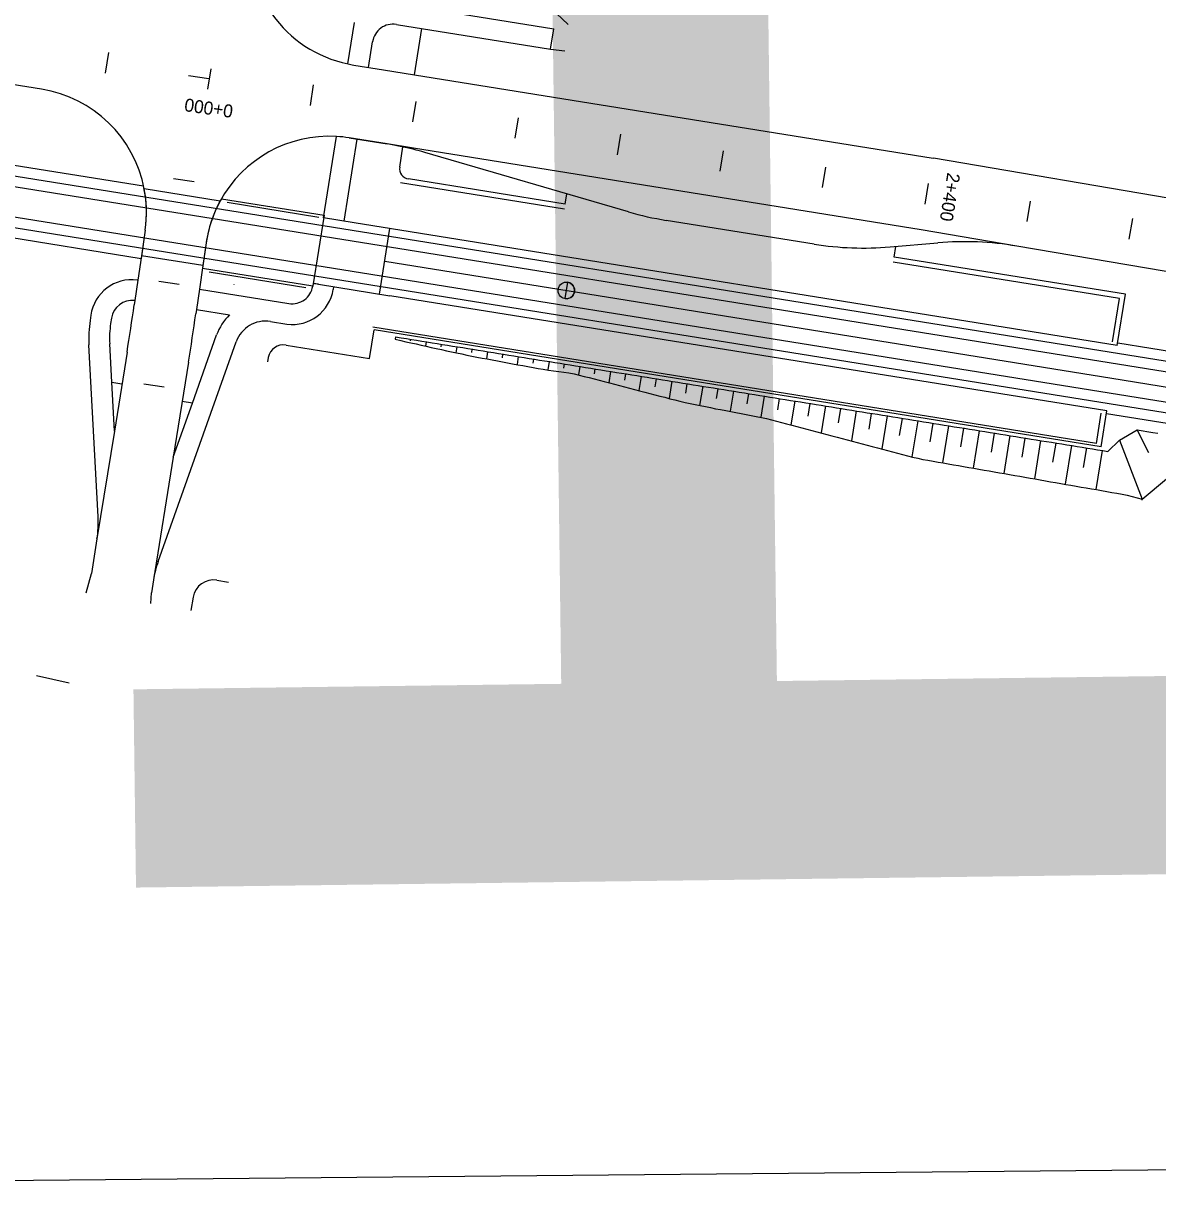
# Model space of a CAD drawing. Extents: x 6503541 to 6503743, y 5888004 to 5888145.
# Drawn here: x 6503648.693 to 6503651.317, y 5888070.651 to 5888073.358 of the extents above; entities that cross this region are included whole.
import ezdxf

# ---------------------------------------------------------------- set-up
doc = ezdxf.new("R2010")
doc.units = 0
doc.layers.add('12', color=7, linetype='Continuous')
doc.layers.add('tabela', color=7, linetype='Continuous')

msp = doc.modelspace()

# ---------------------------------------------------------------- linework, layer by layer
at = {"layer": '12'}
for p, q in [((6503648.7348, 5888073.2052), (6503647.106, 5888073.4639)), ((6503649.8802, 5888073.4242), (6503649.9532, 5888073.355)), ((6503649.5602, 5888073.4031), (6503649.9203, 5888073.3452)), ((6503649.444, 5888073.2637), (6503649.4592, 5888073.3594)), ((6503649.5559, 5888073.3552), (6503649.9127, 5888073.2978)), ((6503649.598, 5888073.2386), (6503649.615, 5888073.3456)), ((6503649.9127, 5888073.2978), (6503649.9203, 5888073.3452)), ((6503646.9543, 5888073.3057), (6503648.9711, 5888072.9816)), ((6503649.4914, 5888073.2559), (6503649.5008, 5888073.3153)), ((6503646.9472, 5888073.2818), (6503653.6193, 5888072.2095)), ((6503649.9127, 5888073.2978), (6503649.9457, 5888073.2938)), ((6503646.9434, 5888073.2581), (6503653.6155, 5888072.1858)), ((6503649.4572, 5888073.2613), (6503649.5263, 5888073.2502)), ((6503649.5263, 5888073.2502), (6503649.598, 5888073.2387)), ((6503649.598, 5888073.2387), (6503650.7981, 5888073.0458)), ((6503646.9323, 5888073.1894), (6503653.6044, 5888072.1171)), ((6503646.9247, 5888073.142), (6503648.9651, 5888072.8141)), ((6503646.9285, 5888073.1657), (6503653.6006, 5888072.0934)), ((6503649.3875, 5888072.9079), (6503649.4174, 5888073.096)), ((6503649.4349, 5888072.9003), (6503649.465, 5888073.0899)), ((6503649.4465, 5888073.0929), (6503649.5345, 5888073.0787)), ((6503649.5345, 5888073.0787), (6503649.4466, 5888073.0928)), ((6503649.5954, 5888073.0689), (6503649.5345, 5888073.0787)), ((6503649.5638, 5888073.0253), (6503649.5712, 5888073.0718)), ((6503650.7703, 5888072.8801), (6503649.5954, 5888073.0689)), ((6503650.093, 5888072.9217), (6503649.6218, 5888073.059)), ((6503650.093, 5888072.9217), (6503649.6218, 5888073.059)), ((6503651.8258, 5888072.8704), (6503650.7985, 5888073.0457)), ((6503649.9446, 5888072.9277), (6503649.5657, 5888072.9886)), ((6503649.9465, 5888072.9396), (6503649.5837, 5888072.9979)), ((6503649.148, 5888072.9464), (6503648.9725, 5888072.9746)), ((6503649.148, 5888072.9464), (6503648.9725, 5888072.9746)), ((6503649.9465, 5888072.9396), (6503649.9503, 5888072.9633)), ((6503649.1511, 5888072.9519), (6503649.3885, 5888072.9138)), ((6503649.1647, 5888072.9437), (6503649.3764, 5888072.9097)), ((6503649.3885, 5888072.9138), (6503649.3625, 5888072.7502)), ((6503649.4586, 5888072.8964), (6503649.3875, 5888072.9079)), ((6503650.5225, 5888072.847), (6503650.1803, 5888072.902)), ((6503650.5225, 5888072.847), (6503650.1803, 5888072.902)), ((6503648.9746, 5888072.8794), (6503648.9651, 5888072.8141)), ((6503648.9746, 5888072.8794), (6503648.966, 5888072.82)), ((6503651.224, 5888072.6127), (6503649.4586, 5888072.8964)), ((6503649.5171, 5888072.7315), (6503649.5412, 5888072.8832)), ((6503650.9914, 5888072.8424), (6503650.7703, 5888072.8801)), ((6503649.1158, 5888072.8499), (6503649.1073, 5888072.7912)), ((6503649.1158, 5888072.8499), (6503649.1082, 5888072.7972)), ((6503650.6983, 5888072.8405), (6503650.8087, 5888072.85)), ((6503650.6983, 5888072.8405), (6503650.8087, 5888072.85)), ((6503648.966, 5888072.82), (6503648.9578, 5888072.7637)), ((6503648.9658, 5888072.8201), (6503648.9658, 5888072.8201)), ((6503649.1082, 5888072.7972), (6503648.966, 5888072.82)), ((6503649.1082, 5888072.7972), (6503648.966, 5888072.82)), ((6503650.7077, 5888072.8172), (6503650.7114, 5888072.8416)), ((6503651.2428, 5888072.7312), (6503650.7077, 5888072.8172)), ((6503651.6589, 5888072.7284), (6503650.9914, 5888072.8424)), ((6503649.1082, 5888072.7972), (6503649.1003, 5888072.743)), ((6503649.1082, 5888072.7972), (6503649.1003, 5888072.743)), ((6503649.1073, 5888072.7912), (6503649.3625, 5888072.7502)), ((6503649.5291, 5888072.8073), (6503651.2114, 5888072.537)), ((6503651.2291, 5888072.7213), (6503650.7058, 5888072.8054)), ((6503648.9578, 5888072.7637), (6503648.9509, 5888072.7162)), ((6503648.9578, 5888072.7637), (6503648.9564, 5888072.7639)), ((6503649.1225, 5888072.7827), (6503649.3461, 5888072.7468)), ((6503649.1003, 5888072.743), (6503649.0934, 5888072.6955)), ((6503649.1003, 5888072.743), (6503649.0934, 5888072.6955)), ((6503649.1003, 5888072.743), (6503649.3074, 5888072.7098)), ((6503649.1003, 5888072.743), (6503649.3074, 5888072.7098)), ((6503649.1803, 5888072.7526), (6503649.1804, 5888072.7533)), ((6503649.3634, 5888072.7558), (6503649.3624, 5888072.7496)), ((6503649.3757, 5888072.7542), (6503649.5411, 5888072.7276)), ((6503649.4108, 5888072.7485), (6503649.4098, 5888072.7422)), ((6503649.4108, 5888072.7485), (6503649.4098, 5888072.7422)), ((6503648.9509, 5888072.7162), (6503648.9495, 5888072.7064)), ((6503648.9509, 5888072.7162), (6503648.9502, 5888072.7163)), ((6503651.1998, 5888072.461), (6503649.5411, 5888072.7276)), ((6503651.2131, 5888072.6208), (6503651.2291, 5888072.7213)), ((6503651.224, 5888072.6127), (6503651.2428, 5888072.7312)), ((6503648.849, 5888072.6825), (6503648.8473, 5888072.6704)), ((6503649.0934, 5888072.6955), (6503649.092, 5888072.6857)), ((6503649.0934, 5888072.6955), (6503649.1698, 5888072.6832)), ((6503649.0934, 5888072.6955), (6503649.1698, 5888072.6832)), ((6503648.8965, 5888072.6756), (6503648.8948, 5888072.6635)), ((6503649.2646, 5888072.668), (6503649.3026, 5888072.6619)), ((6503649.2646, 5888072.668), (6503649.3026, 5888072.6619)), ((6503651.1756, 5888072.3859), (6503649.5018, 5888072.6549)), ((6503649.0839, 5888072.4791), (6503649.1401, 5888072.6371)), ((6503649.0839, 5888072.4791), (6503649.1401, 5888072.6371)), ((6503649.4937, 5888072.5826), (6503649.5043, 5888072.6485)), ((6503649.4937, 5888072.5826), (6503649.5043, 5888072.6485)), ((6503651.1865, 5888072.3781), (6503649.5043, 5888072.6485)), ((6503649.5538, 5888072.6325), (6503649.5529, 5888072.6269)), ((6503648.8659, 5888072.2159), (6503648.8447, 5888072.6137)), ((6503648.8973, 5888072.528), (6503648.8926, 5888072.6162)), ((6503649.0046, 5888072.1126), (6503649.1854, 5888072.621)), ((6503649.0046, 5888072.1126), (6503649.1854, 5888072.621)), ((6503649.3008, 5888072.6136), (6503649.4937, 5888072.5826)), ((6503649.3008, 5888072.6136), (6503649.4937, 5888072.5826)), ((6503649.5887, 5888072.6229), (6503649.5893, 5888072.6268)), ((6503649.6249, 5888072.6211), (6503649.6233, 5888072.6111)), ((6503649.6594, 5888072.6093), (6503649.6604, 5888072.6154)), ((6503649.696, 5888072.6097), (6503649.6937, 5888072.5956)), ((6503649.7302, 5888072.5962), (6503649.7315, 5888072.604)), ((6503651.2249, 5888072.6186), (6503653.6231, 5888072.2332)), ((6503648.9328, 5888072.5969), (6503648.9034, 5888072.4145)), ((6503649.0749, 5888072.574), (6503649.0395, 5888072.354)), ((6503649.2596, 5888072.5846), (6503649.2578, 5888072.5747)), ((6503649.2596, 5888072.5846), (6503649.2578, 5888072.5747)), ((6503649.767, 5888072.5982), (6503649.7644, 5888072.5816)), ((6503649.8012, 5888072.5838), (6503649.8026, 5888072.5925)), ((6503649.8381, 5888072.5868), (6503649.8352, 5888072.5684)), ((6503649.8721, 5888072.5715), (6503649.8737, 5888072.5811)), ((6503649.9092, 5888072.5754), (6503649.9061, 5888072.556)), ((6503649.9433, 5888072.5603), (6503649.9448, 5888072.5697)), ((6503649.9803, 5888072.564), (6503649.9772, 5888072.5446)), ((6503650.014, 5888072.5469), (6503650.0158, 5888072.5583)), ((6503650.0514, 5888072.5525), (6503650.0472, 5888072.5264)), ((6503650.0846, 5888072.532), (6503650.0869, 5888072.5468)), ((6503648.9034, 5888072.4145), (6503648.8973, 5888072.528)), ((6503648.8973, 5888072.528), (6503648.921, 5888072.5241)), ((6503650.1225, 5888072.5411), (6503650.1172, 5888072.5082)), ((6503650.1551, 5888072.5172), (6503650.158, 5888072.5354)), ((6503650.1936, 5888072.5297), (6503650.1872, 5888072.49)), ((6503650.2257, 5888072.5026), (6503650.2291, 5888072.524)), ((6503651.2114, 5888072.537), (6503651.6854, 5888072.4608)), ((6503650.2647, 5888072.5183), (6503650.2575, 5888072.474)), ((6503650.2965, 5888072.4896), (6503650.3002, 5888072.5126)), ((6503650.3357, 5888072.5068), (6503650.3283, 5888072.4603)), ((6503650.3675, 5888072.4773), (6503650.3713, 5888072.5011)), ((6503650.4068, 5888072.4954), (6503650.399, 5888072.4466)), ((6503649.0395, 5888072.354), (6503649.0839, 5888072.4791)), ((6503649.0395, 5888072.354), (6503649.0839, 5888072.4791)), ((6503649.0839, 5888072.4791), (6503649.0603, 5888072.4829)), ((6503650.4382, 5888072.4637), (6503650.4424, 5888072.4897)), ((6503650.4779, 5888072.484), (6503650.469, 5888072.4286)), ((6503650.5087, 5888072.4488), (6503650.5135, 5888072.4783)), ((6503650.549, 5888072.4726), (6503650.539, 5888072.4101)), ((6503650.5793, 5888072.4339), (6503650.5845, 5888072.4669)), ((6503650.6201, 5888072.4611), (6503650.6089, 5888072.3917)), ((6503650.6498, 5888072.419), (6503650.6556, 5888072.4554)), ((6503650.6912, 5888072.4497), (6503650.6789, 5888072.3733)), ((6503650.7203, 5888072.4041), (6503650.7267, 5888072.444)), ((6503650.7623, 5888072.4383), (6503650.7489, 5888072.3549)), ((6503651.1756, 5888072.3859), (6503651.1869, 5888072.4563)), ((6503651.1865, 5888072.3781), (6503651.1998, 5888072.461)), ((6503651.1988, 5888072.4551), (6503653.5968, 5888072.0697)), ((6503648.9034, 5888072.4145), (6503648.8632, 5888072.165)), ((6503650.791, 5888072.3899), (6503650.7978, 5888072.4326)), ((6503650.8334, 5888072.4269), (6503650.8196, 5888072.3411)), ((6503650.862, 5888072.378), (6503650.8689, 5888072.4212)), ((6503650.9044, 5888072.4154), (6503650.8905, 5888072.3287)), ((6503651.2288, 5888072.3937), (6503651.2699, 5888072.4174)), ((6503651.297, 5888072.3643), (6503651.2699, 5888072.4174)), ((6503650.933, 5888072.3661), (6503650.94, 5888072.4097)), ((6503650.9755, 5888072.404), (6503650.9614, 5888072.3164)), ((6503651.004, 5888072.3542), (6503651.0111, 5888072.3983)), ((6503651.0466, 5888072.3926), (6503651.0324, 5888072.304)), ((6503651.075, 5888072.3423), (6503651.0822, 5888072.3869)), ((6503651.2288, 5888072.3937), (6503651.2818, 5888072.2571)), ((6503651.1177, 5888072.3812), (6503651.1033, 5888072.2916)), ((6503651.146, 5888072.3304), (6503651.1533, 5888072.3755)), ((6503651.1888, 5888072.3697), (6503651.1742, 5888072.2792)), ((6503649.0395, 5888072.354), (6503648.9938, 5888072.0704)), ((6503649.0395, 5888072.354), (6503648.9938, 5888072.0704)), ((6503648.8632, 5888072.165), (6503648.8504, 5888072.0852)), ((6503648.8384, 5888072.04), (6503648.8504, 5888072.0852)), ((6503648.9938, 5888072.0704), (6503648.989, 5888072.0405)), ((6503649.1408, 5888072.0696), (6503649.1676, 5888072.0652)), ((6503648.9875, 5888072.0159), (6503648.989, 5888072.0405)), ((6503649.0858, 5888072.0307), (6503649.0801, 5888071.9993)), ((6503648.7229, 5888071.8493), (6503648.7992, 5888071.8323))]:
    msp.add_line(p, q, dxfattribs=at)
for points in [[(6503648.8829, 5888073.2425), (6503648.8904, 5888073.2899)], [(6503649.12, 5888073.2051), (6503649.1275, 5888073.2526)], [(6503649.1224, 5888073.2294), (6503649.0749, 5888073.2363)], [(6503649.3571, 5888073.1678), (6503649.3645, 5888073.2152)], [(6503649.594, 5888073.1299), (6503649.6016, 5888073.1773)], [(6503649.8309, 5888073.0918), (6503649.8386, 5888073.1392)], [(6503650.0679, 5888073.0538), (6503650.0755, 5888073.1011)], [(6503650.3049, 5888073.0157), (6503650.3125, 5888073.0631)], [(6503650.5418, 5888072.9776), (6503650.5494, 5888073.025)], [(6503649.0404, 5888072.9987), (6503649.0879, 5888072.9918)], [(6503650.7864, 5888072.9869), (6503650.7788, 5888072.9395)], [(6503651.0151, 5888072.8992), (6503651.0232, 5888072.9465)], [(6503651.2517, 5888072.8588), (6503651.2598, 5888072.9061)], [(6503649.006, 5888072.7612), (6503649.0535, 5888072.7543)], [(6503649.9522, 5888072.7588), (6503649.9461, 5888072.7209)], [(6503649.5538, 5888072.6325), (6503649.5673, 5888072.6304), (6503649.5791, 5888072.6284), (6503649.591, 5888072.6265), (6503649.6028, 5888072.6246), (6503649.6147, 5888072.6227), (6503649.6265, 5888072.6208), (6503649.6384, 5888072.6189), (6503649.6502, 5888072.617), (6503649.6621, 5888072.6151), (6503649.6739, 5888072.6132), (6503649.6858, 5888072.6113), (6503649.6976, 5888072.6094), (6503649.7095, 5888072.6075), (6503649.7213, 5888072.6056), (6503649.7331, 5888072.6037), (6503649.745, 5888072.6018), (6503649.7568, 5888072.5999), (6503649.7687, 5888072.598), (6503649.7805, 5888072.5961), (6503649.7924, 5888072.5942), (6503649.8042, 5888072.5923), (6503649.8161, 5888072.5904), (6503649.8279, 5888072.5885), (6503649.8398, 5888072.5866), (6503649.8516, 5888072.5847), (6503649.8635, 5888072.5827), (6503649.8753, 5888072.5808), (6503649.8872, 5888072.5789), (6503649.899, 5888072.577), (6503649.9109, 5888072.5751), (6503649.9227, 5888072.5732), (6503649.9346, 5888072.5713), (6503649.9464, 5888072.5694), (6503649.9583, 5888072.5675), (6503649.9701, 5888072.5656), (6503649.982, 5888072.5637), (6503649.9938, 5888072.5618), (6503650.0056, 5888072.5599), (6503650.0175, 5888072.558), (6503650.0293, 5888072.5561), (6503650.0412, 5888072.5542), (6503650.053, 5888072.5523), (6503650.0649, 5888072.5504), (6503650.0767, 5888072.5485), (6503650.0886, 5888072.5466), (6503650.1004, 5888072.5447), (6503650.1123, 5888072.5428), (6503650.1241, 5888072.5409), (6503650.136, 5888072.539), (6503650.1478, 5888072.537), (6503650.1597, 5888072.5351), (6503650.1715, 5888072.5332), (6503650.1834, 5888072.5313), (6503650.1952, 5888072.5294), (6503650.2071, 5888072.5275), (6503650.2189, 5888072.5256), (6503650.2308, 5888072.5237), (6503650.2426, 5888072.5218), (6503650.2545, 5888072.5199), (6503650.2663, 5888072.518), (6503650.2782, 5888072.5161), (6503650.29, 5888072.5142), (6503650.3018, 5888072.5123), (6503650.3137, 5888072.5104), (6503650.3255, 5888072.5085), (6503650.3374, 5888072.5066), (6503650.3492, 5888072.5047), (6503650.3611, 5888072.5028), (6503650.3729, 5888072.5009), (6503650.3848, 5888072.499), (6503650.3966, 5888072.4971), (6503650.4085, 5888072.4952), (6503650.4203, 5888072.4933), (6503650.4322, 5888072.4913), (6503650.444, 5888072.4894), (6503650.4559, 5888072.4875), (6503650.4677, 5888072.4856), (6503650.4796, 5888072.4837), (6503650.4914, 5888072.4818), (6503650.5033, 5888072.4799), (6503650.5151, 5888072.478), (6503650.527, 5888072.4761), (6503650.5388, 5888072.4742), (6503650.5507, 5888072.4723), (6503650.5625, 5888072.4704), (6503650.5744, 5888072.4685), (6503650.5862, 5888072.4666), (6503650.598, 5888072.4647), (6503650.6099, 5888072.4628), (6503650.6217, 5888072.4609), (6503650.6336, 5888072.459), (6503650.6454, 5888072.4571), (6503650.6573, 5888072.4552), (6503650.6691, 5888072.4533), (6503650.681, 5888072.4514), (6503650.6928, 5888072.4495), (6503650.7047, 5888072.4476), (6503650.7165, 5888072.4456), (6503650.7284, 5888072.4437), (6503650.7402, 5888072.4418), (6503650.7521, 5888072.4399), (6503650.7639, 5888072.438), (6503650.7758, 5888072.4361), (6503650.7876, 5888072.4342), (6503650.7995, 5888072.4323), (6503650.8113, 5888072.4304), (6503650.8232, 5888072.4285), (6503650.835, 5888072.4266), (6503650.8469, 5888072.4247), (6503650.8587, 5888072.4228), (6503650.8706, 5888072.4209), (6503650.8824, 5888072.419), (6503650.8942, 5888072.4171), (6503650.9061, 5888072.4152), (6503650.9179, 5888072.4133), (6503650.9298, 5888072.4114), (6503650.9416, 5888072.4095), (6503650.9535, 5888072.4076), (6503650.9653, 5888072.4057), (6503650.9772, 5888072.4038), (6503650.989, 5888072.4019), (6503651.0009, 5888072.3999), (6503651.0127, 5888072.398), (6503651.0246, 5888072.3961), (6503651.0364, 5888072.3942), (6503651.0483, 5888072.3923), (6503651.0601, 5888072.3904), (6503651.072, 5888072.3885), (6503651.0838, 5888072.3866), (6503651.0957, 5888072.3847), (6503651.1075, 5888072.3828), (6503651.1194, 5888072.3809), (6503651.1312, 5888072.379), (6503651.1431, 5888072.3771), (6503651.1549, 5888072.3752), (6503651.1667, 5888072.3733), (6503651.1786, 5888072.3714), (6503651.1904, 5888072.3695), (6503651.2023, 5888072.3676), (6503651.2288, 5888072.3937)], [(6503649.5529, 5888072.6269), (6503649.5662, 5888072.6239), (6503649.578, 5888072.6213), (6503649.5897, 5888072.6187), (6503649.6014, 5888072.616), (6503649.6132, 5888072.6134), (6503649.6249, 5888072.6108), (6503649.6366, 5888072.6081), (6503649.6484, 5888072.6055), (6503649.6601, 5888072.6029), (6503649.6718, 5888072.6003), (6503649.6836, 5888072.5977), (6503649.6953, 5888072.5953), (6503649.7071, 5888072.5929), (6503649.7189, 5888072.5905), (6503649.7306, 5888072.588), (6503649.7424, 5888072.5857), (6503649.7542, 5888072.5835), (6503649.766, 5888072.5813), (6503649.7778, 5888072.5791), (6503649.7896, 5888072.5769), (6503649.8014, 5888072.5747), (6503649.8132, 5888072.5725), (6503649.825, 5888072.5703), (6503649.8368, 5888072.5681), (6503649.8486, 5888072.5659), (6503649.8604, 5888072.5638), (6503649.8722, 5888072.5616), (6503649.884, 5888072.5594), (6503649.8959, 5888072.5575), (6503649.9078, 5888072.5558), (6503649.9196, 5888072.5541), (6503649.9315, 5888072.5524), (6503649.9434, 5888072.5507), (6503649.9553, 5888072.549), (6503649.9671, 5888072.5472), (6503649.9788, 5888072.5441), (6503649.9905, 5888072.5411), (6503650.0021, 5888072.5381), (6503650.0138, 5888072.535), (6503650.0255, 5888072.532), (6503650.0371, 5888072.529), (6503650.0488, 5888072.5259), (6503650.0605, 5888072.5229), (6503650.0721, 5888072.5199), (6503650.0838, 5888072.5168), (6503650.0955, 5888072.5138), (6503650.1071, 5888072.5108), (6503650.1188, 5888072.5077), (6503650.1305, 5888072.5047), (6503650.1421, 5888072.5017), (6503650.1538, 5888072.4986), (6503650.1655, 5888072.4956), (6503650.1771, 5888072.4926), (6503650.1888, 5888072.4895), (6503650.2005, 5888072.4865), (6503650.2121, 5888072.4835), (6503650.2239, 5888072.481), (6503650.2356, 5888072.4785), (6503650.2474, 5888072.4761), (6503650.2592, 5888072.4736), (6503650.2709, 5888072.4712), (6503650.2827, 5888072.4687), (6503650.2945, 5888072.4663), (6503650.3063, 5888072.4643), (6503650.3181, 5888072.4622), (6503650.3299, 5888072.46), (6503650.3417, 5888072.4577), (6503650.3535, 5888072.4554), (6503650.3653, 5888072.4531), (6503650.3771, 5888072.4509), (6503650.3888, 5888072.4486), (6503650.4006, 5888072.4463), (6503650.4123, 5888072.4435), (6503650.424, 5888072.4404), (6503650.4357, 5888072.4373), (6503650.4473, 5888072.4343), (6503650.459, 5888072.4312), (6503650.4706, 5888072.4281), (6503650.4823, 5888072.4251), (6503650.494, 5888072.422), (6503650.5056, 5888072.4189), (6503650.5173, 5888072.4159), (6503650.5289, 5888072.4128), (6503650.5406, 5888072.4097), (6503650.5523, 5888072.4067), (6503650.5639, 5888072.4036), (6503650.5756, 5888072.4005), (6503650.5872, 5888072.3974), (6503650.5989, 5888072.3944), (6503650.6106, 5888072.3913), (6503650.6222, 5888072.3882), (6503650.6339, 5888072.3852), (6503650.6455, 5888072.3821), (6503650.6572, 5888072.379), (6503650.6689, 5888072.376), (6503650.6805, 5888072.3729), (6503650.6922, 5888072.3698), (6503650.7038, 5888072.3668), (6503650.7155, 5888072.3637), (6503650.7272, 5888072.3606), (6503650.7388, 5888072.3575), (6503650.7505, 5888072.3545), (6503650.7622, 5888072.3518), (6503650.7739, 5888072.3491), (6503650.7858, 5888072.347), (6503650.7976, 5888072.345), (6503650.8094, 5888072.3429), (6503650.8212, 5888072.3408), (6503650.833, 5888072.3388), (6503650.8449, 5888072.3367), (6503650.8567, 5888072.3346), (6503650.8685, 5888072.3326), (6503650.8803, 5888072.3305), (6503650.8922, 5888072.3285), (6503650.904, 5888072.3264), (6503650.9158, 5888072.3243), (6503650.9276, 5888072.3223), (6503650.9394, 5888072.3202), (6503650.9513, 5888072.3181), (6503650.9631, 5888072.3161), (6503650.9749, 5888072.314), (6503650.9867, 5888072.312), (6503650.9986, 5888072.3099), (6503651.0104, 5888072.3078), (6503651.0222, 5888072.3058), (6503651.034, 5888072.3037), (6503651.0458, 5888072.3016), (6503651.0577, 5888072.2996), (6503651.0695, 5888072.2975), (6503651.0813, 5888072.2955), (6503651.0931, 5888072.2934), (6503651.105, 5888072.2913), (6503651.1168, 5888072.2893), (6503651.1286, 5888072.2872), (6503651.1404, 5888072.2851), (6503651.1523, 5888072.2831), (6503651.1641, 5888072.281), (6503651.1759, 5888072.279), (6503651.1877, 5888072.2769), (6503651.1995, 5888072.2748), (6503651.2114, 5888072.2728), (6503651.2232, 5888072.2707), (6503651.235, 5888072.2686), (6503651.2468, 5888072.2664), (6503651.2585, 5888072.2633), (6503651.2701, 5888072.2602), (6503651.2818, 5888072.2571)], [(6503648.9715, 5888072.5237), (6503649.019, 5888072.5168)], [(6503651.2699, 5888072.4174), (6503651.3063, 5888072.4116), (6503651.3181, 5888072.4097)], [(6503651.2816, 5888072.2548), (6503651.2816, 5888072.2548), (6503651.2816, 5888072.2548), (6503651.2818, 5888072.2571), (6503651.3376, 5888072.304)]]:
    msp.add_lwpolyline(points, dxfattribs=at)
msp.add_circle((6503649.9492, 5888072.7398), 0.0192, dxfattribs=at)
for centre, radius, start, end in [((6503649.5029, 5888073.5456), 0.288, 173.1984, 258.211), ((6503649.5483, 5888073.3078), 0.048, 80.8698, 170.9745), ((6503649.5029, 5888073.5456), 0.288, 258.211, 260.8698), ((6503648.6896, 5888072.9208), 0.288, 10.7648, 80.9745), ((6503649.4009, 5888072.8085), 0.288, 86.7052, 151.3985), ((6503649.4009, 5888072.8085), 0.288, 80.8698, 86.7052), ((6503649.4009, 5888072.8085), 0.288, 80.8698, 86.7052), ((6503649.4203, 5888072.3678), 0.72, 75.9615, 80.8698), ((6503649.4203, 5888072.3678), 0.72, 75.9615, 80.8698), ((6503649.4203, 5888072.3678), 0.72, 73.7447, 75.9615), ((6503649.4203, 5888072.3678), 0.72, 73.7447, 75.9615), ((6503649.5875, 5888073.0216), 0.024, 170.9745, 260.8698), ((6503648.6896, 5888072.9208), 0.288, 351.7431, 12.1932), ((6503648.6896, 5888072.9208), 0.288, 351.7431, 10.7648), ((6503649.4009, 5888072.8085), 0.288, 150.1274, 171.7431), ((6503649.4009, 5888072.8085), 0.288, 151.3985, 171.7431), ((6503650.2946, 5888073.6129), 0.72, 253.7447, 260.8698), ((6503650.2946, 5888073.6129), 0.72, 253.7447, 260.8698), ((6503650.6367, 5888073.5579), 0.72, 260.8695, 274.906), ((6503650.6367, 5888073.5579), 0.72, 260.8695, 274.906), ((6503650.8703, 5888072.1326), 0.72, 80.3151, 94.906), ((6503650.8703, 5888072.1326), 0.72, 80.3151, 94.906), ((6503648.944, 5888072.6687), 0.096, 82.6164, 171.7431), ((6503649.315, 5888072.7571), 0.096, 262.612, 351.0427), ((6503649.315, 5888072.7571), 0.096, 262.612, 351.0427), ((6503649.315, 5888072.7571), 0.048, 260.8698, 350.9745), ((6503649.315, 5888072.7571), 0.048, 260.8698, 350.9745), ((6503649.3452, 5888072.5646), 0.192, 80.8698, 84.5774), ((6503649.9492, 5888072.7398), 0.0192, 316.4225, 80.8698), ((6503648.944, 5888072.6687), 0.048, 82.6164, 171.7431), ((6503649.9492, 5888072.7398), 0.0192, 260.8698, 316.4225), ((6503641.8954, 5888073.7301), 7.128, 350.85278, 351.74309), ((6503641.8954, 5888073.7301), 7.272, 350.85278, 351.74309), ((6503649.2532, 5888072.5969), 0.12, 133.9999, 160.4332), ((6503649.2532, 5888072.5969), 0.12, 133.9999, 160.4332), ((6503649.1323, 5888072.629), 0.288, 171.7431, 183.053), ((6503649.1323, 5888072.629), 0.24, 171.7431, 183.053), ((6503649.2532, 5888072.5969), 0.072, 80.8698, 160.4332), ((6503649.2532, 5888072.5969), 0.072, 80.8698, 160.4332), ((6503649.295, 5888072.578), 0.036, 80.8698, 169.5715), ((6503649.295, 5888072.578), 0.036, 80.8698, 169.5715), ((6503648.6263, 5888072.2031), 0.24, 350.8528, 3.053), ((6503649.2308, 5888072.0322), 0.24, 160.4332, 170.8528), ((6503649.133, 5888072.0222), 0.048, 80.6697, 169.7995)]:
    msp.add_arc(centre, radius, start, end, dxfattribs=at)
at = {"layer": 'tabela'}
msp.add_line((6503652.7002, 5888070.7182), (6503645.4648, 5888070.6506), dxfattribs=at)
msp.add_line((6503652.7002, 5888070.7182), (6503645.4648, 5888070.6506), dxfattribs=at)

# ---------------------------------------------------------------- texts
at = {"layer": '12'}
for s, height, rotation, p in [('11', 4.22297, 0.7393, (6503645.383, 5888071.3125)), ('0+000', 0.03, 171.7431, (6503649.1797, 5888073.1685)), ('2+400', 0.03, 260.8698, (6503650.831, 5888073.0136))]:
    msp.add_text(s, height=height, rotation=rotation, dxfattribs=at).set_placement(p)

doc.saveas('drawing.dxf')
